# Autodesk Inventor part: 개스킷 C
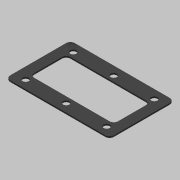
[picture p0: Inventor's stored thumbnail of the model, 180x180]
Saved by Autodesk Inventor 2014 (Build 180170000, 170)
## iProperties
Created: 2020-04
Part Number: 개스킷 C
Material: 고무
Document SubType Name: Modeling
Designer: mduedu
Density: 0.93 g/cm^3
Appearance: 고무 - 검은색 - 버전 1.1
Mass: 1.62617 g
Surface Area: 39.8367 cm^2
Volume: 1.74857 cm^3
Author: mduedu
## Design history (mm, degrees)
sketch "스케치1"
  geometry: L1 (37, 23)-(-37, 23); L2 (-37, 23)-(-37, -23); L3 (-37, -23)-(37, -23); L4 (37, -23)-(37, 23); L5 (37, 23)-(-37, -23); L6 (-37, 23)-(37, -23); L7 (30, 13)-(-30, 13); L8 (-30, 13)-(-30, -13); L9 (-30, -13)-(30, -13); L10 (30, -13)-(30, 13); L11 (30, 13)-(-30, -13); L12 (-30, 13)-(30, -13); 1 further point
  constraints: 24 end point, 4 midpoint, 4 parallel, 2 horizontal, 2 perpendicular
  dimensions: "d0" = 74 distance of L3.end L2.end; "d1" = 46 distance of L2.end L1.end; "d2" = 60 distance of L9.end L8.end; "d3" = 26 distance of L8.end L7.end
extrude "돌출1" new body sketch "스케치1" distance "d4" = 1; taper "d5" = 0 deg
fillet "모깎기1" dims "d6" = 3
fillet "모깎기2" dims "d7" = 3
sketch "스케치2"
  geometry: L1 (-29, -17)-(29, -17); L2 (29, -17)-(29, 17); L3 (29, 17)-(-29, 17); L4 (-29, 17)-(-29, -17); L5 (-29, -17)-(29, 17); L6 (29, -17)-(-29, 17); 7 further points
  constraints: 12 end point, 4 coincident, 4 midpoint, 2 parallel, 1 horizontal, 1 perpendicular
  dimensions: "d8" = 58 distance of L3.end L2.end; "d9" = 34 distance of L2.end L1.end
hole "구멍1" sketch "스케치2" at (-29, 17), (29, 17), (29, -17), (-29, -17), (0, 17), (0, -17) diameter "d10" = 4.5; stored, may be unused: countersink angle "d14" = 90 deg, drill point angle "d16" = 118 deg; dims "d11" = 6, "d12" = 4, "d13" = 2, "d15" = 8
node "솔리드1"
